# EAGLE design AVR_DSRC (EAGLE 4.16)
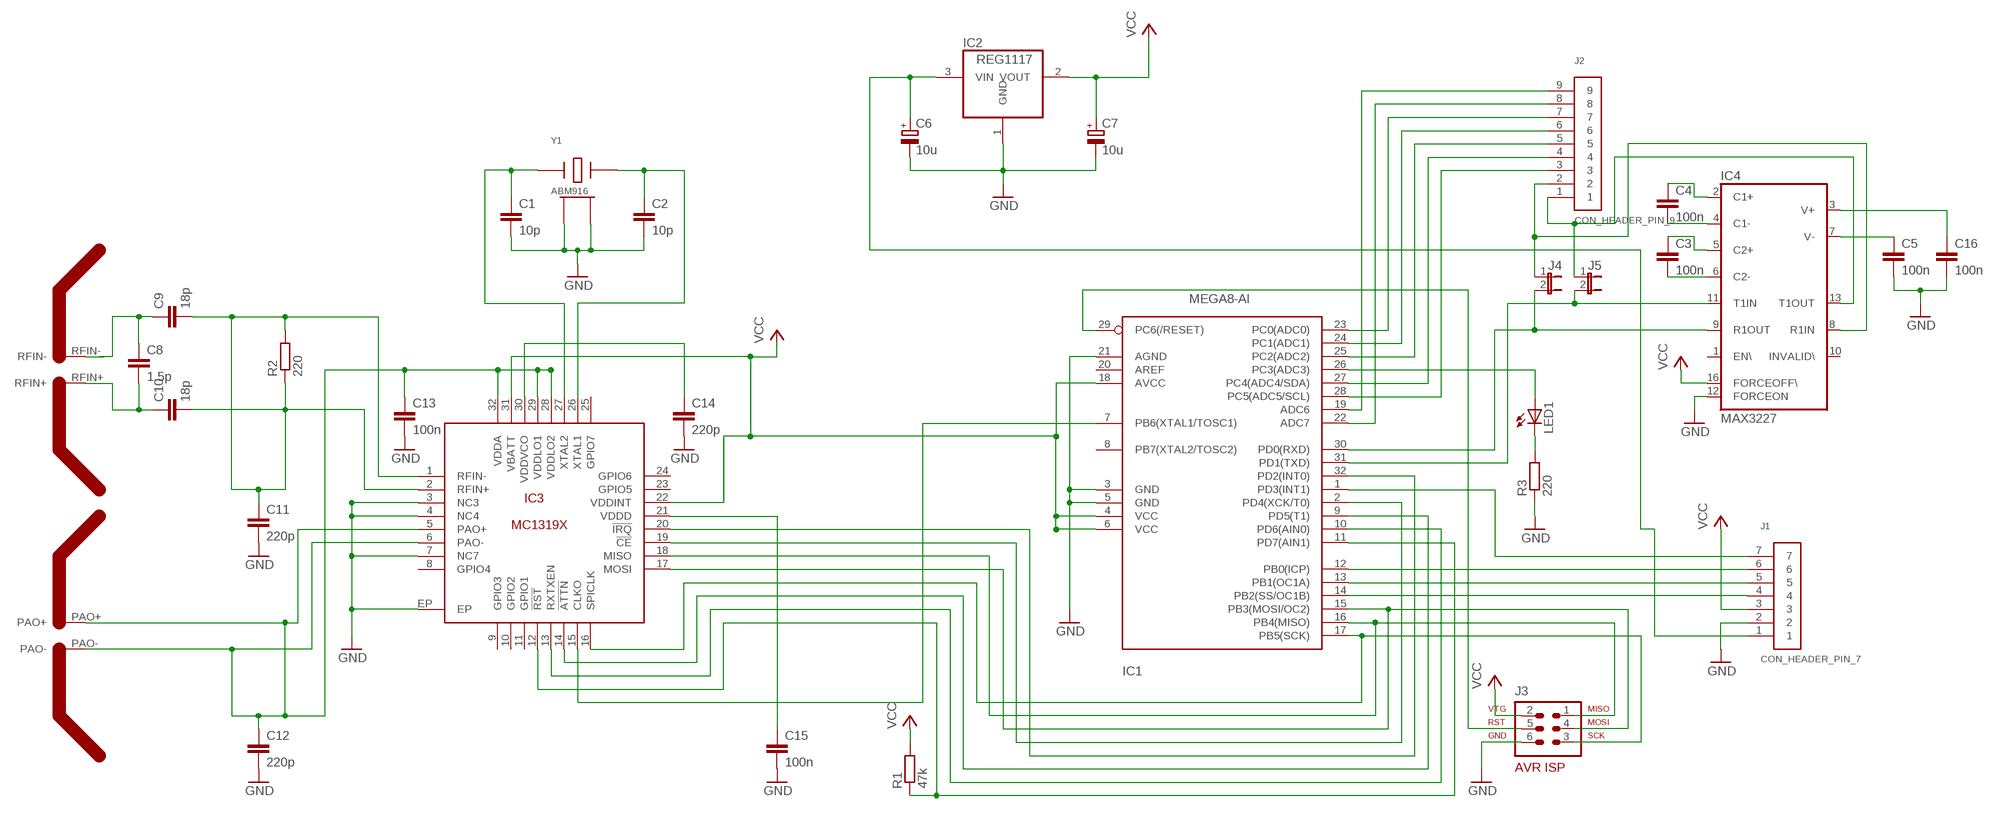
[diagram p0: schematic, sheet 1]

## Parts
ANT  PCBANT1  [PCBANT1]
C1  10p  C-EUC0603K  [C0603K]
C2  10p  C-EUC0603K  [C0603K]
C3  100n  C-EUC0603K  [C0603K]
C4  100n  C-EUC0603K  [C0603K]
C5  100n  C-EUC0603K  [C0603K]
C6  10u  CPOL-EUB/3528-21R  [B/3528-21R]
C7  10u  CPOL-EUB/3528-21R  [B/3528-21R]
C8  1.5p  C-EUC0402K  [C0402K]
C9  18p  C-EUC0402K  [C0402K]
C10  18p  C-EUC0402K  [C0402K]
C11  220p  C-EUC0402K  [C0402K]
C12  220p  C-EUC0402K  [C0402K]
C13  100n  C-EUC0603K  [C0603K]
C14  220p  C-EUC0603K  [C0603K]
C15  100n  C-EUC0603K  [C0603K]
C16  100n  C-EUC0603K  [C0603K]
IC1  MEGA8-AI  [TQFP32-08]
IC2  REG1117  [SOT223]
IC3  MC1319X  [QFN-32EP]
IC4  MAX3227  MAX3221CAE  [SSOP16]
J1  CON_HEADER_PIN_7  [CON_HEADER_PIN_7]
J2  CON_HEADER_PIN_9  [CON_HEADER_PIN_9]
J3  AVR-ISP-6  [AVR-ISP-6]
J4  JP1E  [JP1]
J5  JP1E  [JP1]
LED1  LEDCHIP-LED0603  [CHIP-LED0603]
R1  47k  R-EU_R0603  [R0603]
R2  220  R-EU_R0402  [R0402]
R3  220  R-EU_R0603  [R0603]
Y1  ABM916  [ABM9]

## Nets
GND: C1.2 C2.2 C5.2 C6.- C7.- C11.2 C12.2 C13.2 C14.2 C15.2 C16.2 IC1.3(GND) IC1.5(GND) IC1.21(AGND) IC2.1(GND) IC3.3(NC3) IC3.4(NC4) IC3.7(NC7) IC3.EP IC4.12(FORCEON) J1.2 J3.6 R3.1 Y1.2(GND) Y1.4(GND)
N$1: IC1.15(PB3(MOSI/OC2)) IC3.17(MOSI) J3.4
N$2: IC1.16(PB4(MISO)) IC3.18(MISO) J3.1
N$3: C6.+ IC2.3(VIN) J1.1
N$4: IC1.26(PC3(ADC3)) LED1.A
N$5: IC1.2(PD4(XCK/T0)) IC3.19(!CE)
N$6: IC1.9(PD5(T1)) IC3.14(!ATTN)
N$7: C1.1 IC3.27(XTAL2) Y1.1
N$8: C2.1 IC3.26(XTAL1) Y1.3
N$9: IC1.10(PD6(AIN0)) IC3.13(RXTXEN)
N$10: IC1.7(PB6(XTAL1/TOSC1)) IC3.15(CLKO)
N$11: IC1.17(PB5(SCK)) IC3.16(SPICLK) J3.3
N$12: IC1.32(PD2(INT0)) IC3.20(!IRQ)
N$13: IC1.11(PD7(AIN1)) IC3.12(!RST) R1.1
N$14: IC1.12(PB0(ICP)) J1.6
N$15: IC1.29(PC6(/RESET)) J3.5
N$16: LED1.C R3.2
N$17: IC1.13(PB1(OC1A)) J1.5
N$19: C14.1 IC3.30(VDDVCO)
N$20: ANT.RFIN+ C8.2 C10.1
N$21: C15.1 IC3.21(VDDD)
N$22: C9.2 C10.2 C11.1 IC3.1(RFIN-) IC3.2(RFIN+) R2.1 R2.2
N$23: IC1.14(PB2(SS/OC1B)) J1.4
N$24: ANT.PAO+ ANT.PAO- C12.1 C13.1 IC3.5(PAO+) IC3.6(PAO-) IC3.28(VDDLO2) IC3.29(VDDLO1) IC3.32(VDDA)
N$25: C4.2 IC4.4(C1-)
N$26: C4.1 IC4.2(C1+)
N$27: C3.1 IC4.5(C2+)
N$28: C3.2 IC4.6(C2-)
N$29: C5.1 IC4.7(V-)
N$30: C16.1 IC4.3(V+)
N$31: IC1.19(ADC6) J2.9
N$32: IC1.30(PD0(RXD)) IC4.9(R1OUT) J4.2
N$33: IC1.31(PD1(TXD)) IC4.11(T1IN) J5.2
N$34: IC1.22(ADC7) J2.8
N$35: IC1.23(PC0(ADC0)) J2.7
N$36: IC1.24(PC1(ADC1)) J2.6
N$37: IC1.25(PC2(ADC2)) J2.5
N$38: IC1.27(PC4(ADC4/SDA)) J2.4
N$39: IC1.28(PC5(ADC5/SCL)) J2.3
N$40: IC1.1(PD3(INT1)) J1.7
N$41: IC4.13(T1OUT) J2.1 J5.1
N$42: IC4.8(R1IN) J2.2 J4.1
NETXX: ANT.RFIN- C8.1 C9.1
VCC: C7.+ IC1.4(VCC) IC1.6(VCC) IC1.18(AVCC) IC2.2(VOUT) IC3.22(VDDINT) IC3.31(VBATT) IC4.16(FORCEOFF\) J1.3 J3.2 R1.2
Unconnected: IC1.8(PB7(XTAL2/TOSC2)) IC1.20(AREF) IC3.8(GPIO4) IC3.9(GPIO3) IC3.10(GPIO2) IC3.11(GPIO1) IC3.23(GPIO5) IC3.24(GPIO6) IC3.25(GPIO7) IC4.1(EN\) IC4.10(INVALID\)

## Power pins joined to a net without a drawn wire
GND: IC4.14(GND)
VCC: IC4.15(VCC)

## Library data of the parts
ANT = anteeo:PCBANT1
C1-C5 C8-C16 = rcl:C-EU: CAPACITOR, European symbol
C6 C7 = rcl:CPOL-EU: POLARIZED CAPACITOR, European symbol
IC1 = atmel_2:MEGA8: MICROCONTROLLER 8 Kbytes FLASH 1 kbytes SRAM 512 bytes EEPROM USART 6-channel 10 bit ADC 2-channel 8 bit ADC
IC2 = burr-brown:REG1117: 800mA and 1A Low Dropout (LDO) Positive Regulator 1.8V, 2.5V, 2.85V, 3.3V, 5V, and Adj
IC3 = freescale:MC1319X
IC4 = maxim:MAX3221*: RS-232 Transceivers with AutoShutdown 1µA Supply-Current, True +3V to +5.5V http://dbserv.maxim-ic.com/
J1 = anteeo:CON_HEADER_PIN_7
J2 = anteeo:CON_HEADER_PIN_9
J3 = atmel_2:AVR-ISP-6: AVR ISP-6 Serial Programming Header
J4 J5 = jumper:JP1E: JUMPER
LED1 = led:LED: LED
R1-R3 = rcl:R-EU_: RESISTOR, European symbol
Y1 = abracon:ABM9: 16MHz SMD crystal with low load capacitance

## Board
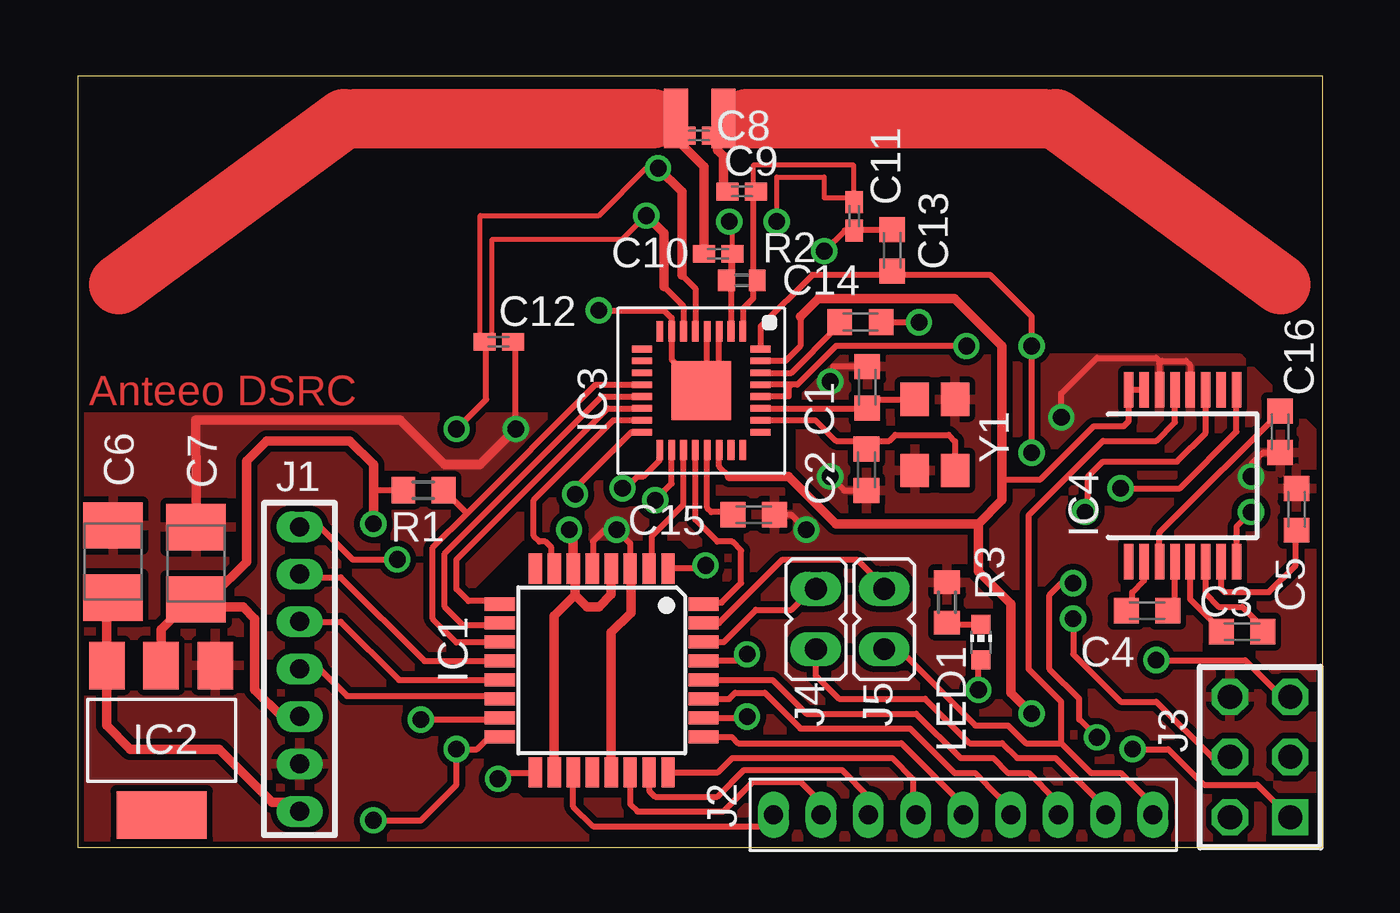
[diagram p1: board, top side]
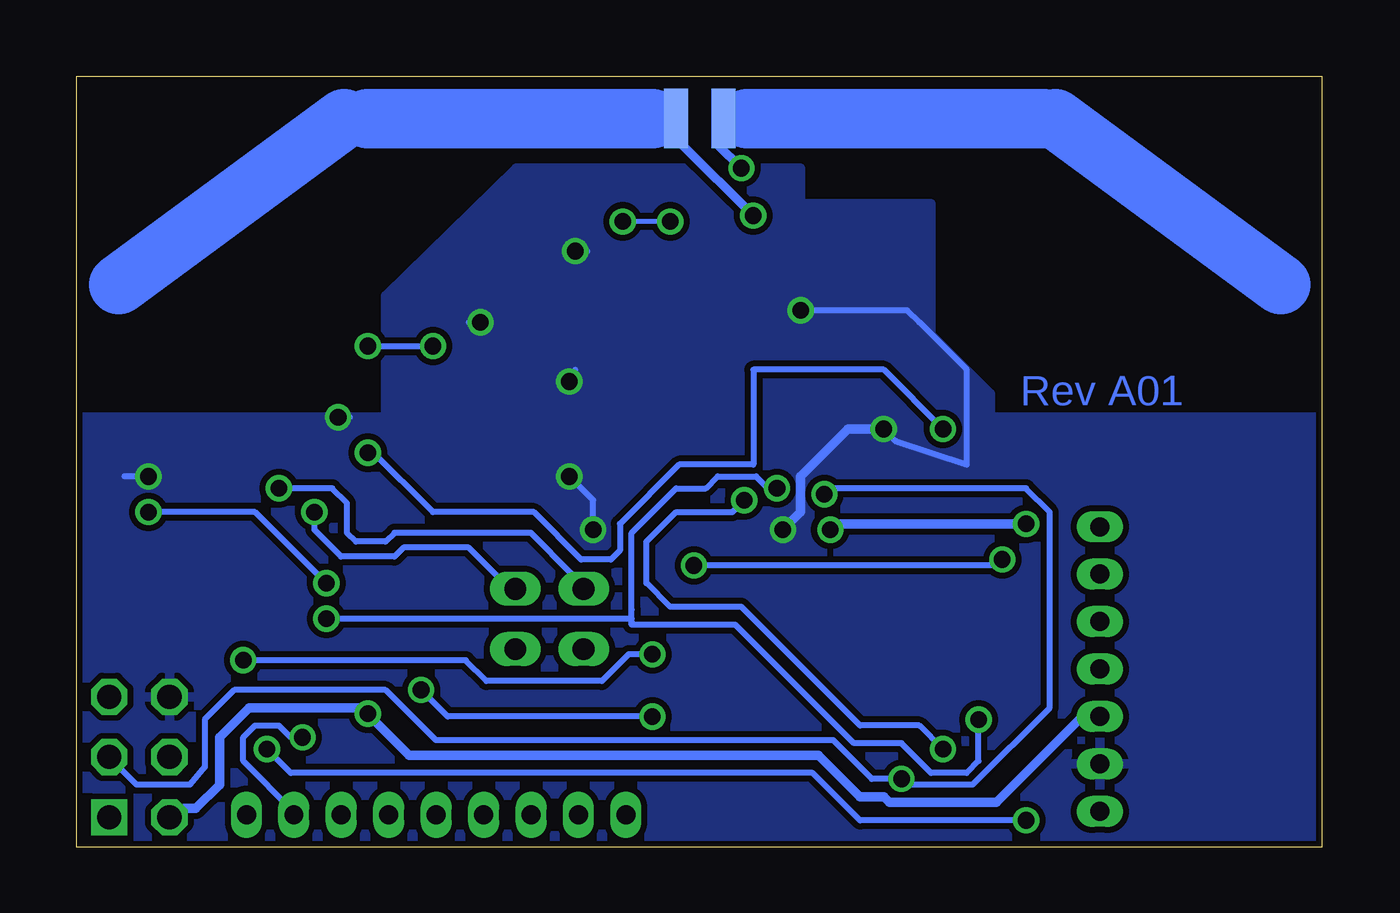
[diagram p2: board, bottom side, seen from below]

Size 52.5 x 32.5 mm. Coordinates in mm from the lower left corner, seen from the top.
Outline: 0,0 52.5,0 52.5,32.5 0,32.5 0,0
Copper layers (1*16): Top 0.035mm / dielectric 1.5mm / Bottom 0.035mm
Design rules "8mils": minimum track width 8mil, minimum drill 24mil, track to track 8mil, track to pad 8mil, pad to pad 8mil, via to via 8mil, smd to smd 8mil, copper to edge 1mil, drill to drill 10mil, minimum pad ring 10mil, minimum via ring 8mil, stop-mask expansion 0mil, vias tented up to drill 0mil, thermal gap 10mil

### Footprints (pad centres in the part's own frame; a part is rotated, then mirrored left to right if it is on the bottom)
PCBANT1 = smd 1 x 2.5 bottom: PAO+ -1,3; PAO- 1,3 | smd 1 x 2.5: RFIN+ -1,3; RFIN- 1,3
C0603K = smd 1.05 x 1.08: 1 -0.875,0; 2 0.875,0
B/3528-21R = smd 1.95 x 2.5: + 1.525,0; - -1.525,0
C0402K = smd 0.925 x 0.74: 1 -0.6,0; 2 0.6,0
TQFP32-08 = smd 1.27 x 0.559: 1 -4.293,2.8; 2 -4.293,2; 3 -4.293,1.2; 4 -4.293,0.4; 5 -4.293,-0.4; 6 -4.293,-1.2; 7 -4.293,-2; 8 -4.293,-2.8; 17 4.293,-2.8; 18 4.293,-2; 19 4.293,-1.2; 20 4.293,-0.4; 21 4.293,0.4; 22 4.293,1.2; 23 4.293,2; 24 4.293,2.8 | smd 0.559 x 1.27: 9 -2.8,-4.293; 10 -2,-4.293; 11 -1.2,-4.293; 12 -0.4,-4.293; 13 0.4,-4.293; 14 1.2,-4.293; 15 2,-4.293; 16 2.8,-4.293; 25 2.8,4.293; 26 2,4.293; 27 1.2,4.293; 28 0.4,4.293; 29 -0.4,4.293; 30 -1.2,4.293; 31 -2,4.293; 32 -2.8,4.293
SOT223 = smd 1.499 x 2.007: 1 -2.261,-3.15; 2 0.025,-3.15; 3 2.311,-3.15 | smd 3.81 x 2.007: 4 0,3.15
QFN-32EP = smd 0.85 x 0.28: 1 -3,3.25; 2 -3,2.75; 3 -3,2.25; 4 -3,1.75; 5 -3,1.25; 6 -3,0.75; 7 -3,0.25; 8 -3,-0.25; 17 2,-0.25; 18 2,0.25; 19 2,0.75; 20 2,1.25; 21 2,1.75; 22 2,2.25; 23 2,2.75; 24 2,3.25 | smd 0.28 x 0.85: 9 -2.25,-1; 10 -1.75,-1; 11 -1.25,-1; 12 -0.75,-1; 13 -0.25,-1; 14 0.25,-1; 15 0.75,-1; 16 1.25,-1; 25 1.25,4; 26 0.75,4; 27 0.25,4; 28 -0.25,4; 29 -0.75,4; 30 -1.25,4; 31 -1.75,4; 32 -2.25,4 | smd 2.5 x 2.5: EP -0.5,1.5
SSOP16 = smd 0.4 x 1.5: 1 -2.275,-3.625; 2 -1.625,-3.625; 3 -0.975,-3.625; 4 -0.325,-3.625; 5 0.325,-3.625; 6 0.975,-3.625; 7 1.625,-3.625; 8 2.275,-3.625; 9 2.275,3.625; 10 1.625,3.625; 11 0.975,3.625; 12 0.325,3.625; 13 -0.325,3.625; 14 -0.975,3.625; 15 -1.625,3.625; 16 -2.275,3.625
CON_HEADER_PIN_7 = drill 0.8 long: 1 -2,-7; 2 -2,-5; 3 -2,-3; 4 -2,-1; 5 -2,1; 6 -2,3; 7 -2,5
CON_HEADER_PIN_9 = drill 0.8 long: 1 0,1; 2 0,3; 3 0,5; 4 0,7; 5 0,9; 6 0,11; 7 0,13; 8 0,15; 9 0,17
AVR-ISP-6 = drill 1.016 square: 1 -2.54,-1.27 | drill 1.016 octagon: 2 -2.54,1.27; 3 0,-1.27; 4 0,1.27; 5 2.54,-1.27; 6 2.54,1.27
JP1 = drill 0.914 long: 1 0,-1.27; 2 0,1.27
CHIP-LED0603 = smd 0.8 x 0.8: A 0,-0.75; C 0,0.75
R0603 = smd 1 x 1.1: 1 -0.85,0; 2 0.85,0
R0402 = smd 0.7 x 0.9: 1 -0.65,0; 2 0.65,0
ABM9 = smd 1.4 x 1.2: 1 -1.5,-0.7; 2 1.5,-0.7; 3 1.5,1; 4 -1.5,1

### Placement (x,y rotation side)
ANT  26.22,27.72 0 top
C1  33.29,19.39 90 top
C2  33.25,15.91 270 top
C3  49.08,9.09 0 top
C4  45.08,9.97 0 top
C5  51.38,14.24 90 top
C6  1.49,12.04 270 top
C7  4.99,11.97 270 top
C8  26.19,30 180 top
C9  28,27.64 0 top
C10  27,25.02 0 top
C11  32.74,26.6 270 top
C12  17.75,21.3 0 top
C13  34.34,25.16 90 top
C14  33,22.14 0 top
C15  28.5,14.02 0 top
C16  50.69,17.52 270 top
IC1  22.09,7.45 270 top
IC2  3.54,4.51 180 top
IC3  24.79,18.75 270 top
IC4  46.58,15.66 0 top
J1  11.35,8.51 0 top
J2  46.34,1.37 90 top
J3  49.85,3.8 90 top
J4  31.12,9.62 0 top
J5  34,9.62 0 top
LED1  38.09,8.65 0 top
R1  14.58,15.05 180 top
R2  28,23.9 0 top
R3  36.65,10.32 270 top
Y1  35.99,17.38 270 top

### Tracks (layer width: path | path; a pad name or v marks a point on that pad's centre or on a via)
GND  (via drill 0.7)
  Top 0.25: IC3.4 26.54,19.2 26.47,19.13 | IC3.3 27.04,19.7 26.47,19.13 | 26.47,19.13 26.35,19.25 IC3.EP | 26.47,19.13 25.04,20.56 IC3.7 25.04,22.31 24.72,22.63 v21.97,22.63 | v31.47,25.13 32.34,26 C11.2 32.74,26.11 | 32.74,26.11 32.72,26.13 | C13.2 32.81,26.04 32.74,26.11 | 33.73,22.14 v35.46,22.14 v35.47,22.13 | 18.47,21.13 18.39,21.21 C12.2
  Top 0.254: 36.97,19.13 36.99,19.11 Y1.4 | 33.73,22.14 C14.2 33.96,22.14 | 33.47,20.13 33.34,20.27 C1.2 31.86,20.27 v31.72,19.63 | 33.96,22.14 33.97,22.13 | 33.96,22.14 33.88,22.23 | C2.2 32.31,15.04 v31.72,15.63 | v18.47,17.63 18.47,21.13 | IC1.3 23.29,12.81 v22.72,13.38 22.22,13.38 21.72,12.88 21.72,11.88 21.69,11.85 IC1.5 | C15.2 30.08,14.02 v30.72,13.38 | C16.2 49.98,16.65 49.48,16.15 v49.47,15.63 | 45.6,20.38 45.6,20.49 45.47,20.63 42.97,20.63 41.47,19.13 v41.47,18.13 | 45.6,20.38 IC4.14 | IC4.12 46.91,20.32 46.72,20.51 45.72,20.51 45.59,20.38 45.6,20.38
  Top 0.406: C7.- 4.98,15.05 4.97,18.01 13.6,18.01 15.47,16.13 16.97,16.13 v18.47,17.63 | IC1.21 22.49,9.05 23.32,9.88 23.32,11.63 23.29,11.66 IC1.3
  Bottom 0.25: v31.47,25.13 30.97,25.13 | v31.72,19.63 31.47,20.13 | v35.47,22.13 35.97,22.13 | v21.97,22.63 17.47,22.63 16.97,22.13 14.97,20.13 14.97,16.13 17.97,17.13 v18.47,17.63
  Bottom 0.254: 31.72,15.88 v31.72,15.63 30.72,14.63 v30.72,13.38 | v22.72,13.38 22.47,13.38 | v49.47,15.63 50.47,15.63 | 40.97,18.13 v41.47,18.13
  Bottom 0.406: v18.47,17.63 19.97,17.63 21.97,15.63 21.97,14.13 v22.72,13.38
  pour Top (isolate 0.254): -0.03,18.13 21.97,18.13 21.97,15.13 30.47,15.13 30.47,20.63 48.97,20.63 52.47,17.13 52.47,0.13 25.47,0.13 25.47,1.88 27.72,4.13 27.72,10.88 25.47,13.13 18.72,13.13 16.47,10.88 16.47,4.13 18.72,1.88 25.22,1.88 25.22,0.13 -0.03,0.13
  pour Bottom (isolate 0.254): -0.03,18.13 13.97,18.13 13.97,19.13 16.47,21.63 16.47,27.13 21.97,27.13 21.97,28.63 33.97,28.63 39.47,23.26 39.47,18.13 52.47,18.13 52.47,0.13 25.72,0.13 26.72,0.13 -0.03,0.13
N$1  (via drill 0.7)
  Top 0.25: IC1.15 17.72,5.38 v14.47,5.38 | IC3.17 24.54,16.33 23.84,15.63 23.59,15.63 23.09,15.13 v22.97,15.13
  Top 0.254: v41.97,9.63 41.97,8.13 43.97,6.13 45.47,6.13 47.84,3.76 48.47,3.76 48.58,3.87 | 48.58,3.87 48.59,3.88 | 48.58,3.87 J3.4
  Bottom 0.25: v22.97,15.13 23.34,15.13 23.84,15.63 25.47,15.63 25.97,15.13 27.22,15.13 29.09,13.26 29.09,9.63 | 24.72,9.38 19.72,4.38 17.72,4.38 16.47,3.13 14.97,3.13 14.47,3.63 v14.47,5.38
  Bottom 0.254: 24.72,9.38 29.09,9.38 | 29.09,9.38 29.09,9.51 | 29.09,9.38 29.09,9.63 | 29.09,9.63 29.09,10.01 | 29.09,9.63 v41.97,9.63
N$2  (via drill 0.7)
  Top 0.25: IC1.16 17.36,4.65 16.84,4.13 v15.97,4.13 | IC3.18 25.04,15.33 v24.34,14.63
  Top 0.254: v15.97,4.13 15.97,2.63 14.47,1.13 v12.47,1.13 | v44.47,4.13 45.97,4.13 47.47,2.63 49.72,2.63 51.09,1.26 J3.1
  Bottom 0.25: v24.34,14.63 24.84,14.13 27.22,14.13 28.47,12.88 28.47,11.13 27.47,10.13 24.47,10.13 19.47,5.13 16.97,5.13 v15.97,4.13
  Bottom 0.254: v12.47,1.13 19.47,1.13 21.47,3.13 43.47,3.13 v44.47,4.13
N$3
  Top 0.406: C6.+ 1.49,10.61 1.47,10.63 1.23,10.39 IC2.3 1.23,7.34 1.22,7.33 1.22,5.13 2.22,4.13 5.97,4.13 8.2,1.9 8.7,1.9 9.22,1.38 J1.1
N$4  (via drill 0.7)
  Top 0.254: IC1.26 28.16,5.45 v28.22,5.51 | LED1.A 37.97,7.76 v37.97,6.63
  Bottom 0.254: v28.22,5.51 36.84,5.51 v37.97,6.63
N$5
  Top 0.25: IC3.19 25.54,14.45 24.22,13.13 24.22,11.88 IC1.2
N$6
  Top 0.25: IC3.14 22.34,18.5 15.97,12.13 15.97,10.88 16.47,10.38 17.72,10.38 17.8,10.3 IC1.9
N$7
  Top 0.25: IC3.27 33.34,18.5 33.47,18.63
  Top 0.254: C1.1 33.35,18.52 33.47,18.63 33.72,18.88 Y1.1
N$8
  Top 0.25: IC3.26 31.1,18 31.97,17.13 32.97,17.13 33.22,16.88
  Top 0.254: Y1.3 36.99,17.11 36.72,17.38 34.47,17.38 34.22,17.13 33.47,17.13 33.22,16.88 33.25,16.85 C2.1
N$9
  Top 0.25: IC3.13 22.09,19 15.47,12.38 15.47,10.13 16.22,9.38 17.72,9.38 IC1.10
N$10
  Top 0.25: IC3.15 22.59,18 19.22,14.63 19.22,13.13 19.47,12.88 19.72,12.88 19.97,12.63 19.97,11.88 20.09,11.76 IC1.7
N$11  (via drill 0.7)
  Top 0.25: IC3.16 23.34,17.5 20.97,15.13 v20.97,14.88 | IC1.17 19.25,3.16 19.22,3.13 17.97,3.13 v17.72,2.88
  Bottom 0.25: v20.97,14.88 20.97,15.13 12.47,15.13 11.47,14.13 11.47,5.88 14.72,2.63 17.47,2.63 v17.72,2.88
  Bottom 0.254: v17.72,2.88 18.97,2.88 20.59,4.51 37.34,4.51 39.47,6.63 45.84,6.63 47.09,5.38 47.09,3.38 47.72,2.63 49.97,2.63 51.12,3.78 J3.3
N$12
  Top 0.25: IC1.32 26.34,10.25 26.22,10.13 26.04,10.31 27.15,10.31 27.97,11.13 27.97,12.51 27.59,12.88 26.97,12.88 26.04,13.81 IC3.20
N$13
  Top 0.25: IC3.12 21.84,19.5 16.41,14.07 | 16.41,14.07 14.97,12.63 14.97,9.63 15.97,8.63 17.72,8.63 17.74,8.65 IC1.11 | 16.41,14.07 R1.1
N$14
  Top 0.254: IC1.12 14.62,7.85 11.1,11.38 9.6,11.38 9.46,11.51 J1.6
N$15  (via drill 0.7)
  Top 0.254: v45.47,7.88 49.22,7.88 50.97,6.13 51.12,6.28 J3.5 | IC1.29 26.44,7.85 26.47,7.88 27.97,7.88 v28.22,8.13
  Bottom 0.254: v28.22,8.13 29.22,8.13 30.34,7.01 35.22,7.01 36.09,7.88 v45.47,7.88
N$16
  Top 0.254: R3.2 36.69,9.47 36.72,9.51 36.82,9.4 LED1.C
N$17
  Top 0.254: IC1.13 13.55,7.05 11.1,9.51 9.72,9.51 9.6,9.38 9.46,9.51 J1.5
N$19
  Top 0.25: IC3.30 30.09,20 31.97,21.88 31.97,22.13 31.98,22.14 C14.1
N$20
  Top 0.406: ANT.RFIN+ 25.22,30.38 C8.2 25.59,29.75 25.47,29.63 26.4,28.7 C10.1
N$21
  Top 0.25: IC3.21 26.54,14.31 26.72,14.13 27.47,14.13 27.58,14.02 C15.1
N$22  (via drill 0.7)
  Top 0.203: C10.2 27.6,26.25 | v29.47,26.38 29.47,28.26 31.47,28.26 31.47,27.38 32.72,27.38 | 28.47,27.63 28.47,28.76 32.72,28.76 32.72,27.38 | C11.1 32.74,27.15 32.72,27.13 32.72,27.38
  Top 0.25: IC3.2 27.54,25.2 27.47,25.13 27.58,25.02 C10.2 27.6,24.26 27.35,24.01 R2.1 | IC3.1 28.04,22.7 28.47,23.13 28.47,24.63 | 28.47,27.63 28.48,27.64 C9.2 28.47,27.64 28.47,27.63 | 28.47,27.63 28.47,24.63 | 27.6,26.25 v27.47,26.38 | 28.7,23.9 28.72,23.88 | 28.7,23.9 R2.2 | 28.47,24.63 28.47,24.13 28.7,23.9
  Bottom 0.203: v27.47,26.38 v29.47,26.38
N$23
  Top 0.254: IC1.14 17.47,6.25 17.34,6.38 11.35,6.38 10.22,7.51 9.47,7.51 9.46,7.51 J1.4
N$24  (via drill 0.7)
  Top 0.203: v23.97,26.63 22.97,25.63 17.47,25.63 17.47,21.63 C12.1 | v24.47,28.63 23.97,28.63 21.97,26.63 16.97,26.63 16.97,21.63 17.15,21.45 C12.1 | 17.22,21.13 17.15,21.2 C12.1
  Top 0.25: IC3.5 26.04,23.56 25.47,24.13 | IC3.6 25.54,22.81 24.72,23.63 | IC3.32 28.79,21.95 30.97,24.13 33.97,24.13 34.22,24.38 34.31,24.29 C13.1 34.34,24.26 34.47,24.13 38.47,24.13 40.22,22.38 v40.22,21.13 | IC3.28 29.97,19 29.97,19.38 30.09,19.5 30.34,19.5 | 30.34,19.5 IC3.29 | 30.34,19.5 31.97,21.13 v37.47,21.13
  Top 0.254: v15.97,17.63 17.22,18.88 17.22,21.13 | v40.22,16.63 v40.22,21.13
  Top 0.406: 25.47,24.13 25.47,27.63 v24.47,28.63 | 24.72,23.63 24.72,25.88 v23.97,26.63
  Bottom 0.25: ANT.PAO+ 25.22,30.63 25.47,30.38 25.47,29.63 | ANT.PAO- 27.22,30.38 26.97,30.13 | v40.22,21.13 v37.47,21.13
  Bottom 0.254: v40.22,16.63 40.09,16.76 37.47,14.13 33.22,14.13 31.22,12.13 29.97,12.13 29.59,12.51 29.59,13.63 27.09,16.13 23.97,16.13 23.97,20.13 18.47,20.13 v15.97,17.63
  Bottom 0.406: v24.47,28.63 25.47,29.63 | v23.97,26.63 26.97,29.63 26.97,30.13
N$25
  Top 0.254: C4.2 46.2,10.12 46.25,10.16 IC4.4
N$26
  Top 0.254: C4.1 44.47,10.13 44.45,10.15 44.45,10.74 44.95,11.24 IC4.2
N$27
  Top 0.254: C3.1 48.2,9.15 46.91,10.45 IC4.5
N$28
  Top 0.254: IC4.6 47.55,10.67 48.09,10.13 49.09,10.13 49.97,9.26 49.95,9.24 C3.2
N$29
  Top 0.254: IC4.7 48.2,10.9 48.34,10.76 50.22,10.76 51.34,11.88 51.34,13.13 51.38,13.16 C5.1
N$30
  Top 0.254: IC4.3 45.6,13.27 50.97,18.63 50.94,18.16 C16.1
N$31
  Top 0.254: IC1.19 20.89,1.71 21.72,0.88 28.84,0.88 J2.9
N$32  (via drill 0.7)
  Top 0.254: IC1.30 27.24,8.65 28.59,10.01 30.09,10.01 30.98,10.89 J4.2 | v43.97,15.13 46.47,15.13 48.85,17.52 IC4.9
  Bottom 0.254: J4.2 31.62,11.53 33.34,13.26 39.09,13.26 39.47,12.88 40.72,12.88 41.09,13.26 41.09,14.51 41.72,15.13 v43.97,15.13
N$33  (via drill 0.7)
  Top 0.254: IC1.31 27.04,9.45 29.72,12.13 32.84,12.13 34,10.98 J5.2 | v42.47,14.13 42.59,14.51 42.59,15.63 43.22,16.26 46.34,16.26 47.55,17.46 IC4.11
  Bottom 0.254: v42.47,14.13 42.47,13.38 41.34,12.26 39.09,12.26 38.72,12.63 35.97,12.63 34.31,10.98 34.06,10.98 33.98,10.89 | 33.98,10.89 33.97,10.88 | J5.2 33.98,10.89
N$34
  Top 0.254: IC1.22 23.29,1.81 23.59,1.51 27.22,1.51 28.47,2.76 30.47,2.76 31.22,2.01 31.22,1.76 31.34,1.63 31.33,1.62 J2.8
N$35
  Top 0.254: IC1.23 24.09,2.39 24.34,2.13 26.97,2.13 28.09,3.26 32.22,3.26 33.34,2.13 33.34,1.51 33.34,1.5 J2.7
N$36
  Top 0.254: IC1.24 27,3.16 27.59,3.76 34.34,3.76 35.22,2.88 35.22,1.76 35.34,1.63 35.34,1.62 J2.6
N$37
  Top 0.254: IC1.25 27.57,4.65 27.84,4.38 34.72,4.38 37.34,1.76 37.34,1.75 J2.5
N$38
  Top 0.254: IC1.27 27.46,6.25 27.72,6.51 28.97,6.51 30.47,5.01 35.09,5.01 36.97,3.13 37.84,3.13 38.84,2.13 39.34,1.38 J2.4
N$39
  Top 0.254: IC1.28 29.3,7.05 30.72,5.63 35.34,5.63 37.22,3.76 38.59,3.76 39.22,3.13 40.09,3.13 41.22,2.01 41.34,1.62 J2.3
N$40  (via drill 0.7)
  Top 0.254: IC1.1 26.33,11.74 v26.47,11.88 | v13.47,12.13 11.6,12.13 10.22,13.51 9.47,13.51 9.46,13.51 J1.7
  Bottom 0.254: v26.47,11.88 13.72,11.88 v13.47,12.13
N$41
  Top 0.254: J5.1 34.62,8.35 37.84,5.13 39.22,5.13 39.97,4.38 41.47,4.38 | J2.1 45.34,1.75 45.34,1.76 43.97,3.13 42.72,3.13 41.47,4.38 | IC4.13 46.25,17.91 45.47,17.13 43.22,17.13 40.09,14.01 40.09,7.51 41.47,6.13 41.47,4.38
N$42  (via drill 0.7)
  Top 0.254: J4.1 31.12,7.23 32.09,6.26 35.72,6.26 37.59,4.38 38.97,4.38 39.59,3.76 41.22,3.76 43.34,1.64 J2.2 | IC4.8 48.85,13.52 v49.47,14.13 | v41.97,11.13 41.47,11.13 40.97,10.63 40.97,7.51 42.22,6.26 42.22,5.38 v42.97,4.63
  Bottom 0.254: v49.47,14.13 44.97,14.13 v41.97,11.13 | v42.97,4.63 43.47,4.63 43.97,5.13 44.97,5.13 45.47,4.63 45.47,3.63 43.34,1.5 J2.2
NETXX
  Top 0.254: 27.22,30 27.22,29.88 | 27.22,30 C8.1 27.04,29.7 26.97,29.63 | ANT.RFIN- 27.22,30 | 27.22,27.88 27.4,27.7 C9.1
  Top 0.406: 26.97,29.63 26.97,29.38 27.22,29.13 27.22,27.88
VCC  (via drill 0.7)
  Top 0.25: v20.72,13.38 20.89,13.21 | 30.47,22.38 30.47,21.13 29.84,20.5 IC3.31 | IC3.22 27.04,16.06 27.47,15.63 | R1.2 12.52,15.05 12.47,15.01
  Top 0.254: 5.15,10.45 4.97,10.13 4.97,10.38 4.99,10.4 C7.+ | 20.97,11.63 20.89,11.71 IC1.6 | 38.97,15.51 40.59,15.51 42.84,17.76 44.09,17.76 44.3,17.96 IC4.16 IC4.15 44.95,19.27 | 44.95,19.27 44.97,19.26 | 44.95,19.27 IC4.15
  Top 0.406: 4.99,10.61 C7.+ 4.99,10.15 4.97,10.13 6.97,10.13 7.47,9.63 7.47,6.63 8.59,5.51 J1.3 | 3.59,7.38 3.47,7.51 3.51,7.55 IC2.2 3.51,9.18 4.97,10.63 4.99,10.61 | IC1.4 22.49,10.65 21.97,10.13 21.47,10.13 20.97,10.63 | 20.97,11.63 20.97,10.63 | 20.89,13.21 IC1.6 | IC1.18 20.09,9.75 20.97,10.63 | 4.99,10.61 5.7,10.61 7.12,12.03 7.12,16.28 7.97,17.13 11.47,17.13 12.47,16.13 12.47,15.01 v12.47,13.63 | 30.47,22.38 31.22,23.13 36.97,23.13 38.97,21.13 38.97,15.51 38.97,14.63 37.97,13.63 | 37.97,13.63 31.97,13.63 29.97,15.63 27.47,15.63 | v40.22,5.63 39.34,6.51 39.34,10.26 37.97,11.63 37.97,13.63
  Bottom 0.406: v12.47,13.63 20.47,13.63 v20.72,13.38 | J3.2 48.58,1.24 48.47,1.13 47.97,1.63 47.47,1.63 46.47,2.63 46.47,4.63 45.22,5.88 40.59,5.88 40.34,5.63 v40.22,5.63 38.47,3.88 21.22,3.88 19.47,2.13 18.47,2.13 18.22,1.88 13.72,1.88 10.1,5.51 9.47,5.51 9.46,5.51 J1.3

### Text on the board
Top: Anteeo DSRC
Bottom: Rev A01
